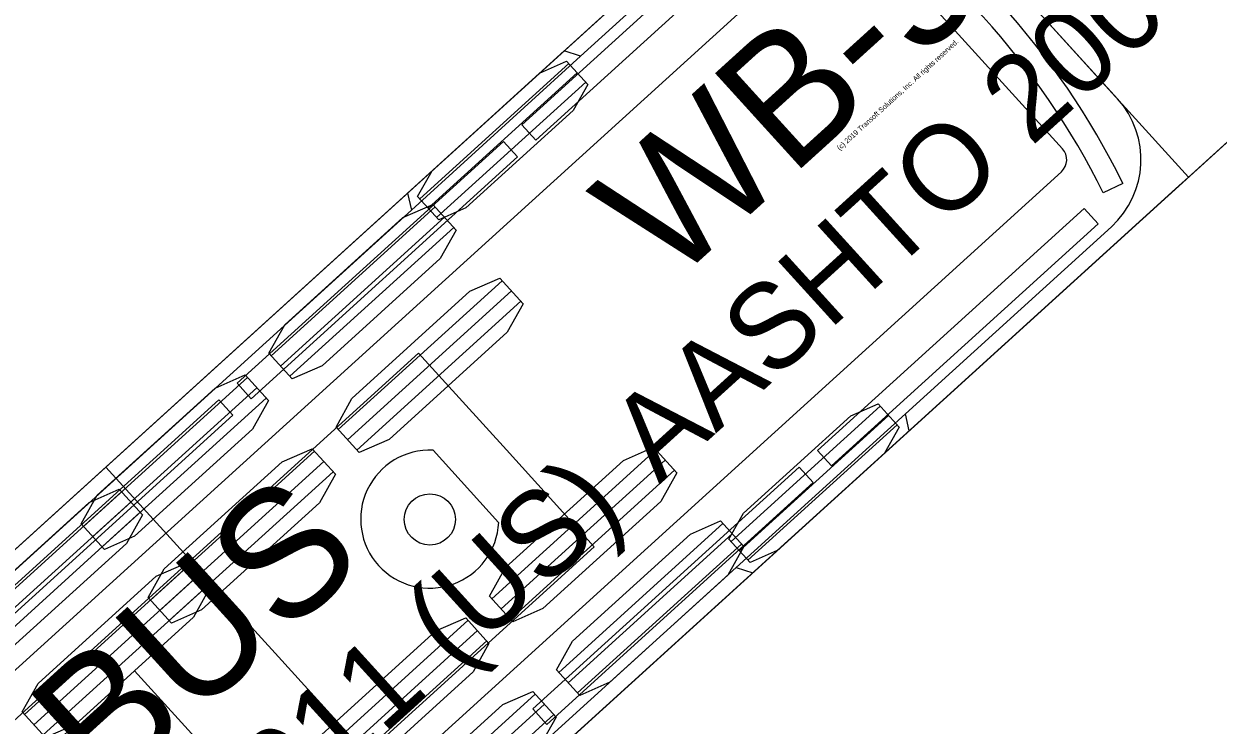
# Model space of a CAD drawing. Extents: x 1639988 to 1641860, y 841974 to 844187.
# Drawn here: x 1640775.68 to 1640795.46, y 844109.81 to 844121.43 of the extents above; entities that cross this region are included whole.
import ezdxf

# ---------------------------------------------------------------- set-up
doc = ezdxf.new("R2010")
doc.units = 0
for name, color, linetype in [('Scratch_Level_1', 7, 'Continuous'), ('Scratch_Level_2', 7, 'Continuous'), ('Scratch_Level_3', 7, 'Continuous'), ('Scratch_Level_4', 7, 'Continuous'), ('Scratch_Level_5', 7, 'Continuous'), ('Scratch_Level_6', 7, 'Continuous')]:
    doc.layers.add(name, color=color, linetype=linetype)

msp = doc.modelspace()

# ---------------------------------------------------------------- linework, layer by layer
at = {"layer": 'Scratch_Level_1'}
for p, q in [((1640803.317, 844137.956), (1640771.858, 844109.38)), ((1640777.573, 844103.088), (1640809.032, 844131.664)), ((1640774.586, 844111.21), (1640777.3, 844113.676)), ((1640774.74, 844111.041), (1640777.454, 844113.506)), ((1640774.894, 844110.871), (1640777.608, 844113.337)), ((1640775.695, 844109.989), (1640778.409, 844112.454)), ((1640775.849, 844109.819), (1640778.563, 844112.285)), ((1640776.003, 844109.65), (1640778.717, 844112.115)), ((1640777.514, 844110.713), (1640770.05, 844103.933)), ((1640779.442, 844108.591), (1640777.514, 844110.713))]:
    msp.add_line(p, q, dxfattribs=at)
for points in [[(1640691.488, 844037.554), (1640695.546, 844040.921), (1640699.578, 844044.326), (1640703.587, 844047.766), (1640707.576, 844051.238), (1640711.547, 844054.738), (1640715.504, 844058.262), (1640723.394, 844065.366), (1640803.317, 844137.956), (1640809.032, 844131.664), (1640808.793, 844131.447), (1640808.793, 844131.447)], [(1640808.793, 844131.447), (1640706.365, 844038.416), (1640702.379, 844034.843), (1640698.36, 844031.302), (1640694.302, 844027.802), (1640690.201, 844024.347), (1640686.055, 844020.942), (1640681.863, 844017.59), (1640677.628, 844014.295), (1640673.351, 844011.058), (1640669.032, 844007.881), (1640664.674, 844004.765), (1640660.276, 844001.71), (1640655.842, 843998.712), (1640651.385, 843995.755), (1640642.436, 843989.91), (1640624.5, 843978.327)]]:
    msp.add_lwpolyline(points, dxfattribs=at)
for points in [[(1640774.932, 844110.829), (1640774.547, 844111.252), (1640774.811, 844111.725), (1640776.766, 844113.5), (1640777.261, 844113.718), (1640777.646, 844113.294), (1640777.382, 844112.822), (1640775.428, 844111.047)], [(1640776.041, 844109.608), (1640775.657, 844110.031), (1640775.921, 844110.504), (1640777.875, 844112.279), (1640778.371, 844112.496), (1640778.755, 844112.073), (1640778.491, 844111.6), (1640776.537, 844109.825)]]:
    msp.add_lwpolyline(points, close=True, dxfattribs=at)
at = {"layer": 'Scratch_Level_2'}
for p, q in [((1640779.779, 844115.928), (1640782.493, 844118.394)), ((1640779.933, 844115.759), (1640782.648, 844118.224)), ((1640780.088, 844115.589), (1640782.802, 844118.054)), ((1640780.889, 844114.707), (1640783.603, 844117.172)), ((1640781.043, 844114.537), (1640783.757, 844117.003)), ((1640781.197, 844114.368), (1640783.911, 844116.833)), ((1640776.67, 844113.104), (1640779.385, 844115.57)), ((1640776.825, 844112.935), (1640779.539, 844115.4)), ((1640776.979, 844112.765), (1640779.693, 844115.23)), ((1640777.78, 844111.883), (1640780.494, 844114.348)), ((1640783.544, 844113.169), (1640782.458, 844114.365)), ((1640783.433, 844111.906), (1640786.147, 844114.372)), ((1640777.934, 844111.713), (1640780.648, 844114.179)), ((1640783.587, 844111.737), (1640786.301, 844114.202)), ((1640783.741, 844111.567), (1640786.455, 844114.033)), ((1640778.088, 844111.544), (1640780.802, 844114.009)), ((1640784.542, 844110.685), (1640787.256, 844113.15)), ((1640784.696, 844110.515), (1640787.41, 844112.981)), ((1640784.85, 844110.346), (1640787.564, 844112.811)), ((1640780.324, 844109.082), (1640783.038, 844111.548)), ((1640780.478, 844108.913), (1640783.192, 844111.378)), ((1640780.632, 844108.743), (1640783.346, 844111.209)), ((1640781.433, 844107.861), (1640784.147, 844110.326)), ((1640781.587, 844107.691), (1640784.301, 844110.157)), ((1640781.741, 844107.522), (1640784.455, 844109.987))]:
    msp.add_line(p, q, dxfattribs=at)
for points in [[(1640691.269, 844038.021), (1640695.364, 844041.343), (1640699.43, 844044.698), (1640703.471, 844048.087), (1640707.491, 844051.508), (1640711.492, 844054.959), (1640715.476, 844058.437), (1640719.446, 844061.939), (1640727.354, 844069.003), (1640735.238, 844076.123), (1640816.27, 844149.722), (1640821.986, 844143.431), (1640821.873, 844143.329), (1640821.873, 844143.329)], [(1640816.233, 844149.658), (1640816.219, 844149.674), (1640816.166, 844149.627), (1640811.971, 844145.817), (1640777.039, 844114.086), (1640779.897, 844110.941), (1640782.754, 844107.795), (1640817.686, 844139.525), (1640821.88, 844143.336), (1640821.933, 844143.384), (1640821.918, 844143.4)], [(1640821.873, 844143.329), (1640711.577, 844043.147), (1640707.605, 844039.571), (1640703.608, 844036.018), (1640699.578, 844032.494), (1640693.5, 844027.235), (1640689.408, 844023.771), (1640685.265, 844020.368), (1640681.075, 844017.026), (1640676.839, 844013.744), (1640672.558, 844010.522), (1640668.235, 844007.361), (1640663.871, 844004.261), (1640659.466, 844001.222), (1640655.021, 843998.244), (1640650.538, 843995.327), (1640648.282, 843993.891), (1640639.353, 843988.021), (1640630.409, 843982.187), (1640612.503, 843970.59)], [(1640773.908, 844109.353), (1640774.369, 844108.846), (1640774.546, 844109.005), (1640782.216, 844115.972), (1640783.672, 844114.37), (1640785.128, 844112.767), (1640777.458, 844105.8), (1640777.282, 844105.639), (1640777.743, 844105.132)]]:
    msp.add_lwpolyline(points, dxfattribs=at)
for points in [[(1640780.126, 844115.547), (1640779.741, 844115.97), (1640780.005, 844116.443), (1640781.959, 844118.218), (1640782.455, 844118.436), (1640782.84, 844118.012), (1640782.576, 844117.54), (1640780.622, 844115.764)], [(1640781.235, 844114.326), (1640780.851, 844114.749), (1640781.115, 844115.222), (1640783.069, 844116.997), (1640783.565, 844117.214), (1640783.949, 844116.791), (1640783.685, 844116.318), (1640781.731, 844114.543)], [(1640777.017, 844112.723), (1640776.632, 844113.146), (1640776.896, 844113.619), (1640778.85, 844115.394), (1640779.346, 844115.612), (1640779.731, 844115.188), (1640779.467, 844114.716), (1640777.513, 844112.941)], [(1640778.126, 844111.502), (1640777.742, 844111.925), (1640778.006, 844112.398), (1640779.96, 844114.173), (1640780.456, 844114.39), (1640780.84, 844113.967), (1640780.576, 844113.494), (1640778.622, 844111.719)], [(1640783.779, 844111.525), (1640783.394, 844111.948), (1640783.658, 844112.421), (1640785.613, 844114.196), (1640786.108, 844114.414), (1640786.493, 844113.99), (1640786.229, 844113.518), (1640784.275, 844111.743)], [(1640784.888, 844110.304), (1640784.504, 844110.727), (1640784.768, 844111.2), (1640786.722, 844112.975), (1640787.218, 844113.193), (1640787.602, 844112.769), (1640787.338, 844112.296), (1640785.384, 844110.521)], [(1640780.67, 844108.701), (1640780.285, 844109.125), (1640780.55, 844109.597), (1640782.504, 844111.372), (1640783, 844111.59), (1640783.384, 844111.166), (1640783.12, 844110.694), (1640781.166, 844108.919)], [(1640781.779, 844107.48), (1640781.395, 844107.903), (1640781.659, 844108.376), (1640783.613, 844110.151), (1640784.109, 844110.369), (1640784.494, 844109.945), (1640784.229, 844109.472), (1640782.275, 844107.697)]]:
    msp.add_lwpolyline(points, close=True, dxfattribs=at)
msp.add_circle((1640782.405, 844113.219), 0.424, dxfattribs=at)
msp.add_arc((1640782.403, 844113.224), 1.143, 87.2506, 357.2506, dxfattribs=at)
at = {"layer": 'Scratch_Level_3'}
for p, q in [((1640779.779, 844115.928), (1640782.493, 844118.394)), ((1640779.933, 844115.759), (1640782.648, 844118.224)), ((1640780.088, 844115.589), (1640782.802, 844118.054)), ((1640780.889, 844114.707), (1640783.603, 844117.172)), ((1640781.043, 844114.537), (1640783.757, 844117.003)), ((1640781.197, 844114.368), (1640783.911, 844116.833)), ((1640776.67, 844113.104), (1640779.385, 844115.57)), ((1640776.825, 844112.935), (1640779.539, 844115.4)), ((1640776.979, 844112.765), (1640779.693, 844115.23)), ((1640777.78, 844111.883), (1640780.494, 844114.348)), ((1640783.544, 844113.169), (1640782.458, 844114.365)), ((1640783.433, 844111.906), (1640786.147, 844114.372)), ((1640777.934, 844111.713), (1640780.648, 844114.179)), ((1640783.587, 844111.737), (1640786.301, 844114.202)), ((1640783.741, 844111.567), (1640786.455, 844114.033)), ((1640778.088, 844111.544), (1640780.802, 844114.009)), ((1640784.542, 844110.685), (1640787.256, 844113.15)), ((1640784.696, 844110.515), (1640787.41, 844112.981)), ((1640784.85, 844110.346), (1640787.564, 844112.811)), ((1640780.324, 844109.082), (1640783.038, 844111.548)), ((1640780.478, 844108.913), (1640783.192, 844111.378)), ((1640780.632, 844108.743), (1640783.346, 844111.209)), ((1640781.433, 844107.861), (1640784.147, 844110.326)), ((1640781.587, 844107.691), (1640784.301, 844110.157)), ((1640781.741, 844107.522), (1640784.455, 844109.987))]:
    msp.add_line(p, q, dxfattribs=at)
for points in [[(1640691.269, 844038.021), (1640695.364, 844041.343), (1640699.43, 844044.698), (1640703.471, 844048.087), (1640707.491, 844051.508), (1640711.492, 844054.959), (1640715.476, 844058.437), (1640719.446, 844061.939), (1640727.354, 844069.003), (1640735.238, 844076.123), (1640816.27, 844149.722), (1640821.986, 844143.431), (1640821.879, 844143.334), (1640821.879, 844143.334)], [(1640816.233, 844149.658), (1640816.219, 844149.674), (1640816.166, 844149.627), (1640811.971, 844145.817), (1640777.039, 844114.086), (1640779.897, 844110.941), (1640782.754, 844107.795), (1640817.686, 844139.525), (1640821.88, 844143.336), (1640821.933, 844143.384), (1640821.918, 844143.4)], [(1640821.879, 844143.334), (1640711.577, 844043.147), (1640707.605, 844039.571), (1640703.608, 844036.018), (1640699.578, 844032.494), (1640693.5, 844027.235), (1640689.408, 844023.771), (1640685.265, 844020.368), (1640681.075, 844017.026), (1640676.839, 844013.744), (1640672.558, 844010.522), (1640668.235, 844007.361), (1640663.871, 844004.261), (1640659.466, 844001.222), (1640655.021, 843998.244), (1640650.538, 843995.327), (1640648.282, 843993.891), (1640639.353, 843988.021), (1640630.409, 843982.187), (1640612.503, 843970.59)], [(1640773.908, 844109.353), (1640774.369, 844108.846), (1640774.546, 844109.005), (1640782.216, 844115.972), (1640783.672, 844114.37), (1640785.128, 844112.767), (1640777.458, 844105.8), (1640777.282, 844105.639), (1640777.743, 844105.132)]]:
    msp.add_lwpolyline(points, dxfattribs=at)
for points in [[(1640780.126, 844115.547), (1640779.741, 844115.97), (1640780.005, 844116.443), (1640781.959, 844118.218), (1640782.455, 844118.436), (1640782.84, 844118.012), (1640782.576, 844117.54), (1640780.622, 844115.764)], [(1640781.235, 844114.326), (1640780.851, 844114.749), (1640781.115, 844115.222), (1640783.069, 844116.997), (1640783.565, 844117.214), (1640783.949, 844116.791), (1640783.685, 844116.318), (1640781.731, 844114.543)], [(1640777.017, 844112.723), (1640776.632, 844113.146), (1640776.896, 844113.619), (1640778.85, 844115.394), (1640779.346, 844115.612), (1640779.731, 844115.188), (1640779.467, 844114.716), (1640777.513, 844112.941)], [(1640778.126, 844111.502), (1640777.742, 844111.925), (1640778.006, 844112.398), (1640779.96, 844114.173), (1640780.456, 844114.39), (1640780.84, 844113.967), (1640780.576, 844113.494), (1640778.622, 844111.719)], [(1640783.779, 844111.525), (1640783.394, 844111.948), (1640783.658, 844112.421), (1640785.613, 844114.196), (1640786.108, 844114.414), (1640786.493, 844113.99), (1640786.229, 844113.518), (1640784.275, 844111.743)], [(1640784.888, 844110.304), (1640784.504, 844110.727), (1640784.768, 844111.2), (1640786.722, 844112.975), (1640787.218, 844113.193), (1640787.602, 844112.769), (1640787.338, 844112.296), (1640785.384, 844110.521)], [(1640780.67, 844108.701), (1640780.285, 844109.125), (1640780.55, 844109.597), (1640782.504, 844111.372), (1640783, 844111.59), (1640783.384, 844111.166), (1640783.12, 844110.694), (1640781.166, 844108.919)], [(1640781.779, 844107.48), (1640781.395, 844107.903), (1640781.659, 844108.376), (1640783.613, 844110.151), (1640784.109, 844110.369), (1640784.494, 844109.945), (1640784.229, 844109.472), (1640782.275, 844107.697)]]:
    msp.add_lwpolyline(points, close=True, dxfattribs=at)
msp.add_circle((1640782.405, 844113.219), 0.424, dxfattribs=at)
msp.add_arc((1640782.403, 844113.224), 1.143, 87.2506, 357.2506, dxfattribs=at)
at = {"layer": 'Scratch_Level_4'}
for p, q in [((1640789.138, 844123.076), (1640762.171, 844098.58)), ((1640792.88, 844119.358), (1640789.52, 844123.058)), ((1640782.099, 844118.343), (1640784.901, 844120.889)), ((1640782.237, 844118.527), (1640784.705, 844120.768)), ((1640782.377, 844118.373), (1640784.845, 844120.614)), ((1640782.517, 844118.218), (1640784.985, 844120.46)), ((1640765.894, 844094.481), (1640792.862, 844118.977)), ((1640787.392, 844112.852), (1640789.86, 844115.093)), ((1640787.476, 844112.423), (1640790.279, 844114.969)), ((1640787.532, 844112.698), (1640790, 844114.939)), ((1640787.672, 844112.543), (1640790.14, 844114.785))]:
    msp.add_line(p, q, dxfattribs=at)
for points in [[(1640629.661, 843992.173), (1640638.519, 843998.049), (1640642.931, 844001.004), (1640647.329, 844003.973), (1640651.71, 844006.96), (1640656.068, 844009.968), (1640660.398, 844013.003), (1640664.693, 844016.071), (1640668.947, 844019.179), (1640673.158, 844022.335), (1640677.332, 844025.544), (1640681.469, 844028.802), (1640685.571, 844032.109), (1640689.639, 844035.462), (1640693.676, 844038.859), (1640697.683, 844042.297), (1640701.666, 844045.773), (1640705.627, 844049.283), (1640709.573, 844052.821), (1640789.253, 844125.181), (1640794.968, 844118.889), (1640794.762, 844118.702), (1640794.762, 844118.702)], [(1640788.311, 844123.986), (1640784.901, 844120.889), (1640784.626, 844120.978), (1640782.036, 844118.625), (1640782.099, 844118.343), (1640766.515, 844104.187), (1640766.121, 844104.169), (1640763.53, 844101.816), (1640763.474, 844101.426)], [(1640793.79, 844120.185), (1640790.43, 844123.884)], [(1640793.88, 844118.783), (1640793.553, 844118.629)], [(1640794.762, 844118.702), (1640731.801, 844061.511), (1640716.025, 844047.15), (1640708.096, 844039.978), (1640700.164, 844032.774), (1640696.182, 844029.177), (1640694.17, 844027.4), (1640692.142, 844025.64), (1640690.1, 844023.895), (1640688.044, 844022.166), (1640685.973, 844020.453), (1640683.889, 844018.756), (1640681.792, 844017.074), (1640677.559, 844013.757), (1640673.278, 844010.502), (1640668.952, 844007.311), (1640664.585, 844004.185), (1640660.181, 844001.125), (1640655.74, 843998.13), (1640651.263, 843995.2), (1640646.749, 843992.333), (1640637.704, 843986.649), (1640628.694, 843980.932)], [(1640766.721, 844093.57), (1640768.852, 844095.506), (1640769.246, 844095.524), (1640771.836, 844097.877), (1640771.892, 844098.267), (1640787.476, 844112.423), (1640787.751, 844112.333), (1640790.342, 844114.687), (1640790.279, 844114.969), (1640793.689, 844118.066)]]:
    msp.add_lwpolyline(points, dxfattribs=at)
for points in [[(1640788.569, 844123.507), (1640788.337, 844123.762), (1640783.926, 844119.755), (1640784.158, 844119.5)], [(1640782.552, 844118.18), (1640782.203, 844118.565), (1640782.443, 844118.995), (1640784.219, 844120.609), (1640784.67, 844120.806), (1640785.02, 844120.421), (1640784.779, 844119.992), (1640783.003, 844118.378)], [(1640783.855, 844119.225), (1640783.623, 844119.48), (1640779.212, 844115.473), (1640779.444, 844115.218)], [(1640793.236, 844118.369), (1640793.468, 844118.114), (1640789.056, 844114.106), (1640788.825, 844114.362)], [(1640774.73, 844110.936), (1640774.498, 844111.191), (1640778.909, 844115.198), (1640779.141, 844114.943)], [(1640787.707, 844112.505), (1640787.357, 844112.89), (1640787.598, 844113.32), (1640789.374, 844114.934), (1640789.825, 844115.131), (1640790.174, 844114.746), (1640789.934, 844114.317), (1640788.158, 844112.703)], [(1640788.522, 844114.087), (1640788.754, 844113.832), (1640784.342, 844109.824), (1640784.111, 844110.08)]]:
    msp.add_lwpolyline(points, close=True, dxfattribs=at)
for centre, radius, start, end in [((1640782.159, 844112.995), 13.073, 26.2777, 58.2235), ((1640782.159, 844112.995), 12.711, 26.3078, 58.1933), ((1640792.68, 844119.177), 1.5, 312.2506, 42.2506), ((1640792.68, 844119.177), 0.27, 312.2506, 42.2506)]:
    msp.add_arc(centre, radius, start, end, dxfattribs=at)
at = {"layer": 'Scratch_Level_5'}
for p, q in [((1640789.138, 844123.076), (1640762.171, 844098.58)), ((1640792.88, 844119.358), (1640789.52, 844123.058)), ((1640782.099, 844118.343), (1640784.901, 844120.889)), ((1640782.237, 844118.527), (1640784.705, 844120.768)), ((1640782.377, 844118.373), (1640784.845, 844120.614)), ((1640782.517, 844118.218), (1640784.985, 844120.46)), ((1640765.894, 844094.481), (1640792.862, 844118.977)), ((1640787.392, 844112.852), (1640789.86, 844115.093)), ((1640787.476, 844112.423), (1640790.279, 844114.969)), ((1640787.532, 844112.698), (1640790, 844114.939)), ((1640787.672, 844112.543), (1640790.14, 844114.785))]:
    msp.add_line(p, q, dxfattribs=at)
for points in [[(1640629.661, 843992.173), (1640638.519, 843998.049), (1640642.931, 844001.004), (1640647.329, 844003.973), (1640651.71, 844006.96), (1640656.068, 844009.968), (1640660.398, 844013.003), (1640664.693, 844016.071), (1640668.947, 844019.179), (1640673.158, 844022.335), (1640677.332, 844025.544), (1640681.469, 844028.802), (1640685.571, 844032.109), (1640689.639, 844035.462), (1640693.676, 844038.859), (1640697.683, 844042.297), (1640701.666, 844045.773), (1640705.627, 844049.283), (1640709.573, 844052.821), (1640789.253, 844125.181), (1640794.968, 844118.889)], [(1640788.311, 844123.986), (1640784.901, 844120.889), (1640784.626, 844120.978), (1640782.036, 844118.625), (1640782.099, 844118.343), (1640766.515, 844104.187), (1640766.121, 844104.169), (1640763.53, 844101.816), (1640763.474, 844101.426)], [(1640793.79, 844120.185), (1640790.43, 844123.884)], [(1640793.88, 844118.783), (1640793.553, 844118.629)], [(1640794.968, 844118.889), (1640794.753, 844118.694), (1640794.753, 844118.694)], [(1640794.753, 844118.694), (1640731.801, 844061.511), (1640716.025, 844047.15), (1640708.096, 844039.978), (1640700.164, 844032.774), (1640696.182, 844029.177), (1640694.17, 844027.4), (1640692.142, 844025.64), (1640690.1, 844023.895), (1640688.044, 844022.166), (1640685.973, 844020.453), (1640683.889, 844018.756), (1640681.792, 844017.074), (1640677.559, 844013.757), (1640673.278, 844010.502), (1640668.952, 844007.311), (1640664.585, 844004.185), (1640660.181, 844001.125), (1640655.74, 843998.13), (1640651.263, 843995.2), (1640646.749, 843992.333), (1640637.704, 843986.649), (1640628.694, 843980.932)], [(1640766.721, 844093.57), (1640768.852, 844095.506), (1640769.246, 844095.524), (1640771.836, 844097.877), (1640771.892, 844098.267), (1640787.476, 844112.423), (1640787.751, 844112.333), (1640790.342, 844114.687), (1640790.279, 844114.969), (1640793.689, 844118.066)]]:
    msp.add_lwpolyline(points, dxfattribs=at)
for points in [[(1640788.569, 844123.507), (1640788.337, 844123.762), (1640783.926, 844119.755), (1640784.158, 844119.5)], [(1640782.552, 844118.18), (1640782.203, 844118.565), (1640782.443, 844118.995), (1640784.219, 844120.609), (1640784.67, 844120.806), (1640785.02, 844120.421), (1640784.779, 844119.992), (1640783.003, 844118.378)], [(1640783.855, 844119.225), (1640783.623, 844119.48), (1640779.212, 844115.473), (1640779.444, 844115.218)], [(1640793.236, 844118.369), (1640793.468, 844118.114), (1640789.056, 844114.106), (1640788.825, 844114.362)], [(1640774.73, 844110.936), (1640774.498, 844111.191), (1640778.909, 844115.198), (1640779.141, 844114.943)], [(1640787.707, 844112.505), (1640787.357, 844112.89), (1640787.598, 844113.32), (1640789.374, 844114.934), (1640789.825, 844115.131), (1640790.174, 844114.746), (1640789.934, 844114.317), (1640788.158, 844112.703)], [(1640788.522, 844114.087), (1640788.754, 844113.832), (1640784.342, 844109.824), (1640784.111, 844110.08)]]:
    msp.add_lwpolyline(points, close=True, dxfattribs=at)
for centre, radius, start, end in [((1640782.159, 844112.995), 13.073, 26.2777, 58.2235), ((1640782.159, 844112.995), 12.711, 26.3078, 58.1933), ((1640792.68, 844119.177), 1.5, 312.2506, 42.2506), ((1640792.68, 844119.177), 0.27, 312.2506, 42.2506)]:
    msp.add_arc(centre, radius, start, end, dxfattribs=at)
at = {"layer": 'Scratch_Level_6'}
for p, q in [((1640789.138, 844123.076), (1640762.171, 844098.58)), ((1640792.88, 844119.358), (1640789.52, 844123.058)), ((1640782.099, 844118.343), (1640784.901, 844120.889)), ((1640782.237, 844118.527), (1640784.705, 844120.768)), ((1640782.377, 844118.373), (1640784.845, 844120.614)), ((1640782.517, 844118.218), (1640784.985, 844120.46)), ((1640765.894, 844094.481), (1640792.862, 844118.977)), ((1640787.392, 844112.852), (1640789.86, 844115.093)), ((1640787.476, 844112.423), (1640790.279, 844114.969)), ((1640787.532, 844112.698), (1640790, 844114.939)), ((1640787.672, 844112.543), (1640790.14, 844114.785))]:
    msp.add_line(p, q, dxfattribs=at)
for points in [[(1640629.661, 843992.173), (1640638.519, 843998.049), (1640642.931, 844001.004), (1640647.329, 844003.973), (1640651.71, 844006.96), (1640656.068, 844009.968), (1640660.398, 844013.003), (1640664.693, 844016.071), (1640668.947, 844019.179), (1640673.158, 844022.335), (1640677.332, 844025.544), (1640681.469, 844028.802), (1640685.571, 844032.109), (1640689.639, 844035.462), (1640693.676, 844038.859), (1640697.683, 844042.297), (1640701.666, 844045.773), (1640705.627, 844049.283), (1640709.573, 844052.821), (1640789.253, 844125.181), (1640794.968, 844118.889), (1640794.776, 844118.715), (1640794.776, 844118.715)], [(1640788.311, 844123.986), (1640784.901, 844120.889), (1640784.626, 844120.978), (1640782.036, 844118.625), (1640782.099, 844118.343), (1640766.515, 844104.187), (1640766.121, 844104.169), (1640763.53, 844101.816), (1640763.474, 844101.426)], [(1640793.79, 844120.185), (1640790.43, 844123.884)], [(1640793.88, 844118.783), (1640793.553, 844118.629)], [(1640794.776, 844118.715), (1640731.801, 844061.511), (1640716.025, 844047.15), (1640708.096, 844039.978), (1640700.164, 844032.774), (1640696.182, 844029.177), (1640694.17, 844027.4), (1640692.142, 844025.64), (1640690.1, 844023.895), (1640688.044, 844022.166), (1640685.973, 844020.453), (1640683.889, 844018.756), (1640681.792, 844017.074), (1640677.559, 844013.757), (1640673.278, 844010.502), (1640668.952, 844007.311), (1640664.585, 844004.185), (1640660.181, 844001.125), (1640655.74, 843998.13), (1640651.263, 843995.2), (1640646.749, 843992.333), (1640637.704, 843986.649), (1640628.694, 843980.932)], [(1640766.721, 844093.57), (1640768.852, 844095.506), (1640769.246, 844095.524), (1640771.836, 844097.877), (1640771.892, 844098.267), (1640787.476, 844112.423), (1640787.751, 844112.333), (1640790.342, 844114.687), (1640790.279, 844114.969), (1640793.689, 844118.066)]]:
    msp.add_lwpolyline(points, dxfattribs=at)
for points in [[(1640788.569, 844123.507), (1640788.337, 844123.762), (1640783.926, 844119.755), (1640784.158, 844119.5)], [(1640782.552, 844118.18), (1640782.203, 844118.565), (1640782.443, 844118.995), (1640784.219, 844120.609), (1640784.67, 844120.806), (1640785.02, 844120.421), (1640784.779, 844119.992), (1640783.003, 844118.378)], [(1640783.855, 844119.225), (1640783.623, 844119.48), (1640779.212, 844115.473), (1640779.444, 844115.218)], [(1640793.236, 844118.369), (1640793.468, 844118.114), (1640789.056, 844114.106), (1640788.825, 844114.362)], [(1640774.73, 844110.936), (1640774.498, 844111.191), (1640778.909, 844115.198), (1640779.141, 844114.943)], [(1640787.707, 844112.505), (1640787.357, 844112.89), (1640787.598, 844113.32), (1640789.374, 844114.934), (1640789.825, 844115.131), (1640790.174, 844114.746), (1640789.934, 844114.317), (1640788.158, 844112.703)], [(1640788.522, 844114.087), (1640788.754, 844113.832), (1640784.342, 844109.824), (1640784.111, 844110.08)]]:
    msp.add_lwpolyline(points, close=True, dxfattribs=at)
for centre, radius, start, end in [((1640782.159, 844112.995), 13.073, 26.2777, 58.2235), ((1640782.159, 844112.995), 12.711, 26.3078, 58.1933), ((1640792.68, 844119.177), 1.5, 312.2506, 42.2506), ((1640792.68, 844119.177), 0.27, 312.2506, 42.2506)]:
    msp.add_arc(centre, radius, start, end, dxfattribs=at)

# ---------------------------------------------------------------- texts
at = {"layer": 'Scratch_Level_1'}
for s, height, p in [('AASHTO 2001 (US)', 1.41667, (1640786.204, 844113.79)), ('WB-50', 2.125, (1640786.398, 844117.076)), ('(c) 2019 Transoft Solutions, Inc. All rights reserved.', 0.085, (1640789.191, 844119.326))]:
    msp.add_text(s, height=height, rotation=42.2506, dxfattribs=at).set_placement(p)
at = {"layer": 'Scratch_Level_4'}
for s, height, p in [('AASHTO 2011 (US)', 1.41667, (1640773.141, 844101.923)), ('CITY-BUS', 2.125, (1640771.574, 844103.61))]:
    msp.add_text(s, height=height, rotation=42.2506, dxfattribs=at).set_placement(p)
at = {"layer": 'Scratch_Level_5'}
for s, height, p in [('AASHTO 2011 (US)', 1.41667, (1640773.141, 844101.923)), ('CITY-BUS', 2.125, (1640771.574, 844103.61))]:
    msp.add_text(s, height=height, rotation=42.2506, dxfattribs=at).set_placement(p)
at = {"layer": 'Scratch_Level_6'}
for s, height, p in [('AASHTO 2011 (US)', 1.41667, (1640773.141, 844101.923)), ('CITY-BUS', 2.125, (1640771.574, 844103.61))]:
    msp.add_text(s, height=height, rotation=42.2506, dxfattribs=at).set_placement(p)

doc.saveas('drawing.dxf')
